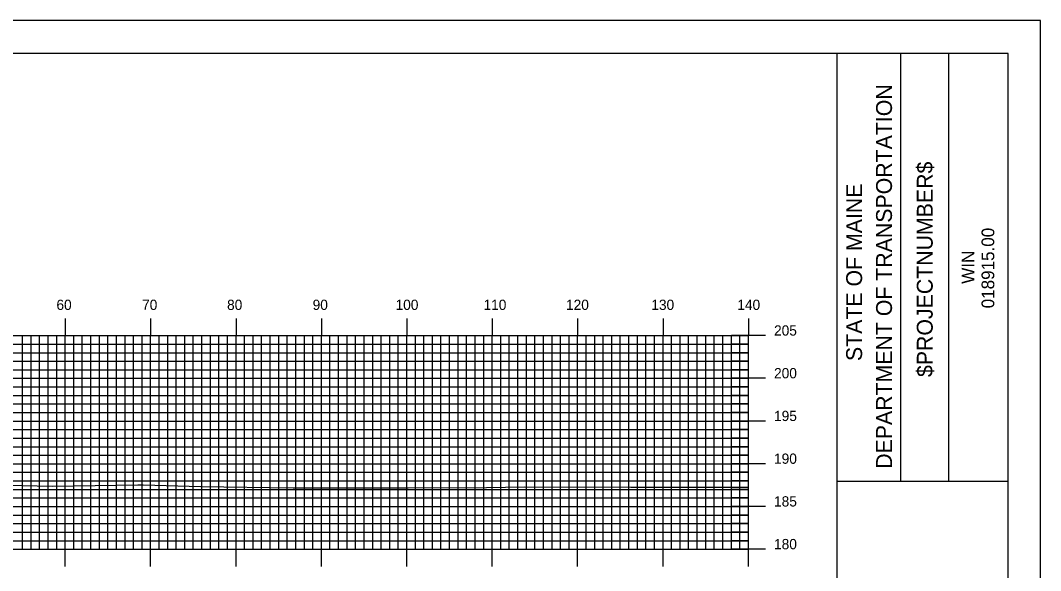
# Model space of a CAD drawing. Extents: x 1822392 to 1822735, y 442591 to 442811.
# Drawn here: x 1822612.5 to 1822732, y 442746.2 to 442810.5 of the extents above; entities that cross this region are included whole.
import ezdxf

# ---------------------------------------------------------------- set-up
doc = ezdxf.new("R2010")
doc.units = 0
for name, color, linetype in [('BORDER', 7, 'Continuous'), ('H_V ANNOTATION', 7, 'Continuous'), ('MAJOR', 7, 'Continuous'), ('MINOR', 7, 'Continuous'), ('PLOT BOUNDARY', 7, 'Continuous'), ('S_Roadway_Centerline', 7, 'Continuous')]:
    doc.layers.add(name, color=color, linetype=linetype)

msp = doc.modelspace()

# ---------------------------------------------------------------- linework, layer by layer
at = {"layer": 'BORDER'}
for p, q in [((1822708.17, 442596.67), (1822708.17, 442806.67)), ((1822715.63, 442756.66), (1822715.63, 442806.66)), ((1822721.22, 442756.66), (1822721.22, 442806.66)), ((1822708.17, 442756.65), (1822728.17, 442756.65))]:
    msp.add_line(p, q, dxfattribs=at)
msp.add_lwpolyline([(1822408.17, 442596.67), (1822728.17, 442596.67), (1822728.17, 442806.67), (1822408.17, 442806.67)], close=True, dxfattribs=at)
at = {"layer": 'MAJOR'}
for p, q in [((1822617.77, 442775.67), (1822617.77, 442773.67)), ((1822627.77, 442775.67), (1822627.77, 442773.67)), ((1822637.77, 442775.67), (1822637.77, 442773.67)), ((1822647.77, 442775.67), (1822647.77, 442773.67)), ((1822657.77, 442775.67), (1822657.77, 442773.67)), ((1822667.77, 442775.67), (1822667.77, 442773.67)), ((1822677.77, 442775.67), (1822677.77, 442773.67)), ((1822687.77, 442775.67), (1822687.77, 442773.67)), ((1822697.77, 442775.67), (1822697.77, 442773.67)), ((1822417.77, 442773.67), (1822697.77, 442773.67)), ((1822417.77, 442773.67), (1822697.77, 442773.67)), ((1822617.77, 442748.67), (1822617.77, 442773.67)), ((1822627.77, 442748.67), (1822627.77, 442773.67)), ((1822637.77, 442748.67), (1822637.77, 442773.67)), ((1822647.77, 442748.67), (1822647.77, 442773.67)), ((1822657.77, 442748.67), (1822657.77, 442773.67)), ((1822667.77, 442748.67), (1822667.77, 442773.67)), ((1822677.77, 442748.67), (1822677.77, 442773.67)), ((1822687.77, 442748.67), (1822687.77, 442773.67)), ((1822699.77, 442773.67), (1822695.77, 442773.67)), ((1822697.77, 442748.67), (1822697.77, 442773.67)), ((1822697.77, 442748.67), (1822697.77, 442773.67)), ((1822417.77, 442768.67), (1822697.77, 442768.67)), ((1822699.77, 442768.67), (1822695.77, 442768.67)), ((1822417.77, 442763.67), (1822697.77, 442763.67)), ((1822699.77, 442763.67), (1822695.77, 442763.67)), ((1822417.77, 442758.67), (1822697.77, 442758.67)), ((1822699.77, 442758.67), (1822695.77, 442758.67)), ((1822417.77, 442753.67), (1822697.77, 442753.67)), ((1822699.77, 442753.67), (1822695.77, 442753.67)), ((1822417.77, 442748.67), (1822697.77, 442748.67)), ((1822417.77, 442748.67), (1822697.77, 442748.67)), ((1822617.77, 442746.66), (1822617.77, 442748.67)), ((1822627.77, 442746.66), (1822627.77, 442748.67)), ((1822637.77, 442746.66), (1822637.77, 442748.67)), ((1822647.77, 442746.66), (1822647.77, 442748.67)), ((1822657.77, 442746.66), (1822657.77, 442748.67)), ((1822667.77, 442746.66), (1822667.77, 442748.67)), ((1822677.77, 442746.66), (1822677.77, 442748.67)), ((1822687.77, 442746.66), (1822687.77, 442748.67)), ((1822699.77, 442748.67), (1822695.77, 442748.67)), ((1822697.77, 442746.66), (1822697.77, 442748.67))]:
    msp.add_line(p, q, dxfattribs=at)
at = {"layer": 'MINOR'}
for p, q in [((1822612.77, 442748.67), (1822612.77, 442773.67)), ((1822613.77, 442748.67), (1822613.77, 442773.67)), ((1822614.77, 442748.67), (1822614.77, 442773.67)), ((1822615.77, 442748.67), (1822615.77, 442773.67)), ((1822616.77, 442748.67), (1822616.77, 442773.67)), ((1822618.77, 442748.67), (1822618.77, 442773.67)), ((1822619.77, 442748.67), (1822619.77, 442773.67)), ((1822620.77, 442748.67), (1822620.77, 442773.67)), ((1822621.77, 442748.67), (1822621.77, 442773.67)), ((1822622.77, 442748.67), (1822622.77, 442773.67)), ((1822623.77, 442748.67), (1822623.77, 442773.67)), ((1822624.77, 442748.67), (1822624.77, 442773.67)), ((1822625.77, 442748.67), (1822625.77, 442773.67)), ((1822626.77, 442748.67), (1822626.77, 442773.67)), ((1822628.77, 442748.67), (1822628.77, 442773.67)), ((1822629.77, 442748.67), (1822629.77, 442773.67)), ((1822630.77, 442748.67), (1822630.77, 442773.67)), ((1822631.77, 442748.67), (1822631.77, 442773.67)), ((1822632.77, 442748.67), (1822632.77, 442773.67)), ((1822633.77, 442748.67), (1822633.77, 442773.67)), ((1822634.77, 442748.67), (1822634.77, 442773.67)), ((1822635.77, 442748.67), (1822635.77, 442773.67)), ((1822636.77, 442748.67), (1822636.77, 442773.67)), ((1822638.77, 442748.67), (1822638.77, 442773.67)), ((1822639.77, 442748.67), (1822639.77, 442773.67)), ((1822640.77, 442748.67), (1822640.77, 442773.67)), ((1822641.77, 442748.67), (1822641.77, 442773.67)), ((1822642.77, 442748.67), (1822642.77, 442773.67)), ((1822643.77, 442748.67), (1822643.77, 442773.67)), ((1822644.77, 442748.67), (1822644.77, 442773.67)), ((1822645.77, 442748.67), (1822645.77, 442773.67)), ((1822646.77, 442748.67), (1822646.77, 442773.67)), ((1822648.77, 442748.67), (1822648.77, 442773.67)), ((1822649.77, 442748.67), (1822649.77, 442773.67)), ((1822650.77, 442748.67), (1822650.77, 442773.67)), ((1822651.77, 442748.67), (1822651.77, 442773.67)), ((1822652.77, 442748.67), (1822652.77, 442773.67)), ((1822653.77, 442748.67), (1822653.77, 442773.67)), ((1822654.77, 442748.67), (1822654.77, 442773.67)), ((1822655.77, 442748.67), (1822655.77, 442773.67)), ((1822656.77, 442748.67), (1822656.77, 442773.67)), ((1822658.77, 442748.67), (1822658.77, 442773.67)), ((1822659.77, 442748.67), (1822659.77, 442773.67)), ((1822660.77, 442748.67), (1822660.77, 442773.67)), ((1822661.77, 442748.67), (1822661.77, 442773.67)), ((1822662.77, 442748.67), (1822662.77, 442773.67)), ((1822663.77, 442748.67), (1822663.77, 442773.67)), ((1822664.77, 442748.67), (1822664.77, 442773.67)), ((1822665.77, 442748.67), (1822665.77, 442773.67)), ((1822666.77, 442748.67), (1822666.77, 442773.67)), ((1822668.77, 442748.67), (1822668.77, 442773.67)), ((1822669.77, 442748.67), (1822669.77, 442773.67)), ((1822670.77, 442748.67), (1822670.77, 442773.67)), ((1822671.77, 442748.67), (1822671.77, 442773.67)), ((1822672.77, 442748.67), (1822672.77, 442773.67)), ((1822673.77, 442748.67), (1822673.77, 442773.67)), ((1822674.77, 442748.67), (1822674.77, 442773.67)), ((1822675.77, 442748.67), (1822675.77, 442773.67)), ((1822676.77, 442748.67), (1822676.77, 442773.67)), ((1822678.77, 442748.67), (1822678.77, 442773.67)), ((1822679.77, 442748.67), (1822679.77, 442773.67)), ((1822680.77, 442748.67), (1822680.77, 442773.67)), ((1822681.77, 442748.67), (1822681.77, 442773.67)), ((1822682.77, 442748.67), (1822682.77, 442773.67)), ((1822683.77, 442748.67), (1822683.77, 442773.67)), ((1822684.77, 442748.67), (1822684.77, 442773.67)), ((1822685.77, 442748.67), (1822685.77, 442773.67)), ((1822686.77, 442748.67), (1822686.77, 442773.67)), ((1822688.77, 442748.67), (1822688.77, 442773.67)), ((1822689.77, 442748.67), (1822689.77, 442773.67)), ((1822690.77, 442748.67), (1822690.77, 442773.67)), ((1822691.77, 442748.67), (1822691.77, 442773.67)), ((1822692.77, 442748.67), (1822692.77, 442773.67)), ((1822693.77, 442748.67), (1822693.77, 442773.67)), ((1822694.77, 442748.67), (1822694.77, 442773.67)), ((1822695.77, 442748.67), (1822695.77, 442773.67)), ((1822696.77, 442748.67), (1822696.77, 442773.67)), ((1822417.77, 442772.67), (1822697.77, 442772.67)), ((1822417.77, 442771.67), (1822697.77, 442771.67)), ((1822697.77, 442772.67), (1822695.77, 442772.67)), ((1822697.77, 442771.67), (1822695.77, 442771.67)), ((1822417.77, 442770.67), (1822697.77, 442770.67)), ((1822697.77, 442770.67), (1822695.77, 442770.67)), ((1822417.77, 442769.67), (1822697.77, 442769.67)), ((1822697.77, 442769.67), (1822695.77, 442769.67)), ((1822417.77, 442767.67), (1822697.77, 442767.67)), ((1822697.77, 442767.67), (1822695.77, 442767.67)), ((1822417.77, 442766.67), (1822697.77, 442766.67)), ((1822417.77, 442765.67), (1822697.77, 442765.67)), ((1822697.77, 442766.67), (1822695.77, 442766.67)), ((1822697.77, 442765.67), (1822695.77, 442765.67)), ((1822417.77, 442764.67), (1822697.77, 442764.67)), ((1822697.77, 442764.67), (1822695.77, 442764.67)), ((1822417.77, 442762.67), (1822697.77, 442762.67)), ((1822697.77, 442762.67), (1822695.77, 442762.67)), ((1822417.77, 442761.67), (1822697.77, 442761.67)), ((1822697.77, 442761.67), (1822695.77, 442761.67)), ((1822417.77, 442760.67), (1822697.77, 442760.67)), ((1822417.77, 442759.67), (1822697.77, 442759.67)), ((1822697.77, 442760.67), (1822695.77, 442760.67)), ((1822697.77, 442759.67), (1822695.77, 442759.67)), ((1822417.77, 442757.67), (1822697.77, 442757.67)), ((1822697.77, 442757.67), (1822695.77, 442757.67)), ((1822417.77, 442756.67), (1822697.77, 442756.67)), ((1822697.77, 442756.67), (1822695.77, 442756.67)), ((1822417.77, 442755.67), (1822697.77, 442755.67)), ((1822697.77, 442755.67), (1822695.77, 442755.67)), ((1822417.77, 442754.67), (1822697.77, 442754.67)), ((1822697.77, 442754.67), (1822695.77, 442754.67)), ((1822417.77, 442752.67), (1822697.77, 442752.67)), ((1822697.77, 442752.67), (1822695.77, 442752.67)), ((1822417.77, 442751.67), (1822697.77, 442751.67)), ((1822697.77, 442751.67), (1822695.77, 442751.67)), ((1822417.77, 442750.67), (1822697.77, 442750.67)), ((1822697.77, 442750.67), (1822695.77, 442750.67)), ((1822417.77, 442749.67), (1822697.77, 442749.67)), ((1822697.77, 442749.67), (1822695.77, 442749.67))]:
    msp.add_line(p, q, dxfattribs=at)
at = {"layer": 'PLOT BOUNDARY'}
msp.add_lwpolyline([(1822391.98, 442590.55), (1822731.98, 442590.55), (1822731.98, 442810.55), (1822391.98, 442810.55)], close=True, dxfattribs=at)
at = {"layer": 'S_Roadway_Centerline'}
msp.add_lwpolyline([(1822603.75, 442756.31), (1822616.29, 442756.06), (1822626.28, 442756.19), (1822626.77, 442756.2), (1822626.89, 442756.2), (1822633.64, 442756), (1822644.45, 442755.87), (1822649.98, 442755.87), (1822657.94, 442755.85), (1822667.08, 442755.91), (1822671.53, 442755.97), (1822684, 442755.95), (1822684.97, 442755.93), (1822688.17, 442755.93), (1822697.77, 442755.93)], dxfattribs=at)

# ---------------------------------------------------------------- texts
at = {"layer": 'BORDER'}
for s, height, p in [('DEPARTMENT OF TRANSPORTATION', 1.8635, (1822714.58, 442758.08)), ('$PROJECTNUMBER$', 1.8635, (1822719.35, 442768.82)), ('STATE OF MAINE', 1.8635, (1822711.08, 442770.69)), ('018915.00', 1.491, (1822726.56, 442776.86)), ('WIN', 1.491, (1822724.24, 442779.73))]:
    msp.add_text(s, height=height, rotation=90, dxfattribs=at).set_placement(p)
at = {"layer": 'H_V ANNOTATION'}
for s, p in [('60', (1822616.74, 442776.67)), ('70', (1822626.77, 442776.67)), ('80', (1822636.72, 442776.67)), ('90', (1822646.74, 442776.67)), ('100', (1822656.45, 442776.67)), ('110', (1822666.75, 442776.67)), ('120', (1822676.41, 442776.67)), ('130', (1822686.4, 442776.67)), ('140', (1822696.47, 442776.67)), ('205', (1822700.77, 442773.67)), ('200', (1822700.77, 442768.67)), ('195', (1822700.77, 442763.67)), ('190', (1822700.77, 442758.67)), ('185', (1822700.77, 442753.67)), ('180', (1822700.77, 442748.67))]:
    msp.add_text(s, height=1.2, dxfattribs=at).set_placement(p)

doc.saveas('drawing.dxf')
